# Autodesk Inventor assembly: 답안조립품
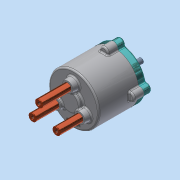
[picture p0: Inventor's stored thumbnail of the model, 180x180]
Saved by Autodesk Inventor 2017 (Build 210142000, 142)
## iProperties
Part Number: 답안조립품
Material: 일반
Document SubType Name: Assembly
Designer: MRC
Author: MRC
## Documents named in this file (14)
- C:\Users\MRC\Desktop\610708V1012\답안조립품.iam
- C:\Users\MRC\Desktop\610708V1012\본체.ipt
- C:\Users\MRC\Desktop\610708V1012\가변스프링-01.ipt
- C:\Users\MRC\Desktop\610708V1012\가변스프링-02.ipt
- C:\Users\MRC\Desktop\610708V1012\가변스프링-03.ipt
- C:\Users\MRC\Desktop\610708V1012\멈춤링 10 x 1.ipt
- C:\Users\MRC\Desktop\610708V1012\멈춤링 22 x 1.2.ipt
- C:\Users\MRC\Desktop\610708V1012\메인 축.ipt
- C:\Users\MRC\Desktop\610708V1012\베어링 NA 4900.ipt
- C:\Users\MRC\Desktop\610708V1012\볼트 M5.ipt
- C:\Users\MRC\Desktop\610708V1012\슬라이드 축.ipt
- C:\Users\MRC\Desktop\610708V1012\오일실.ipt
- C:\Users\MRC\Desktop\610708V1012\커버.ipt
- C:\Users\MRC\Desktop\610708V1012\판캠.ipt
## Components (3 placed, 3 different names)
1. 가변스프링-01:1
2. 가변스프링-02:1
3. 가변스프링-03:1
